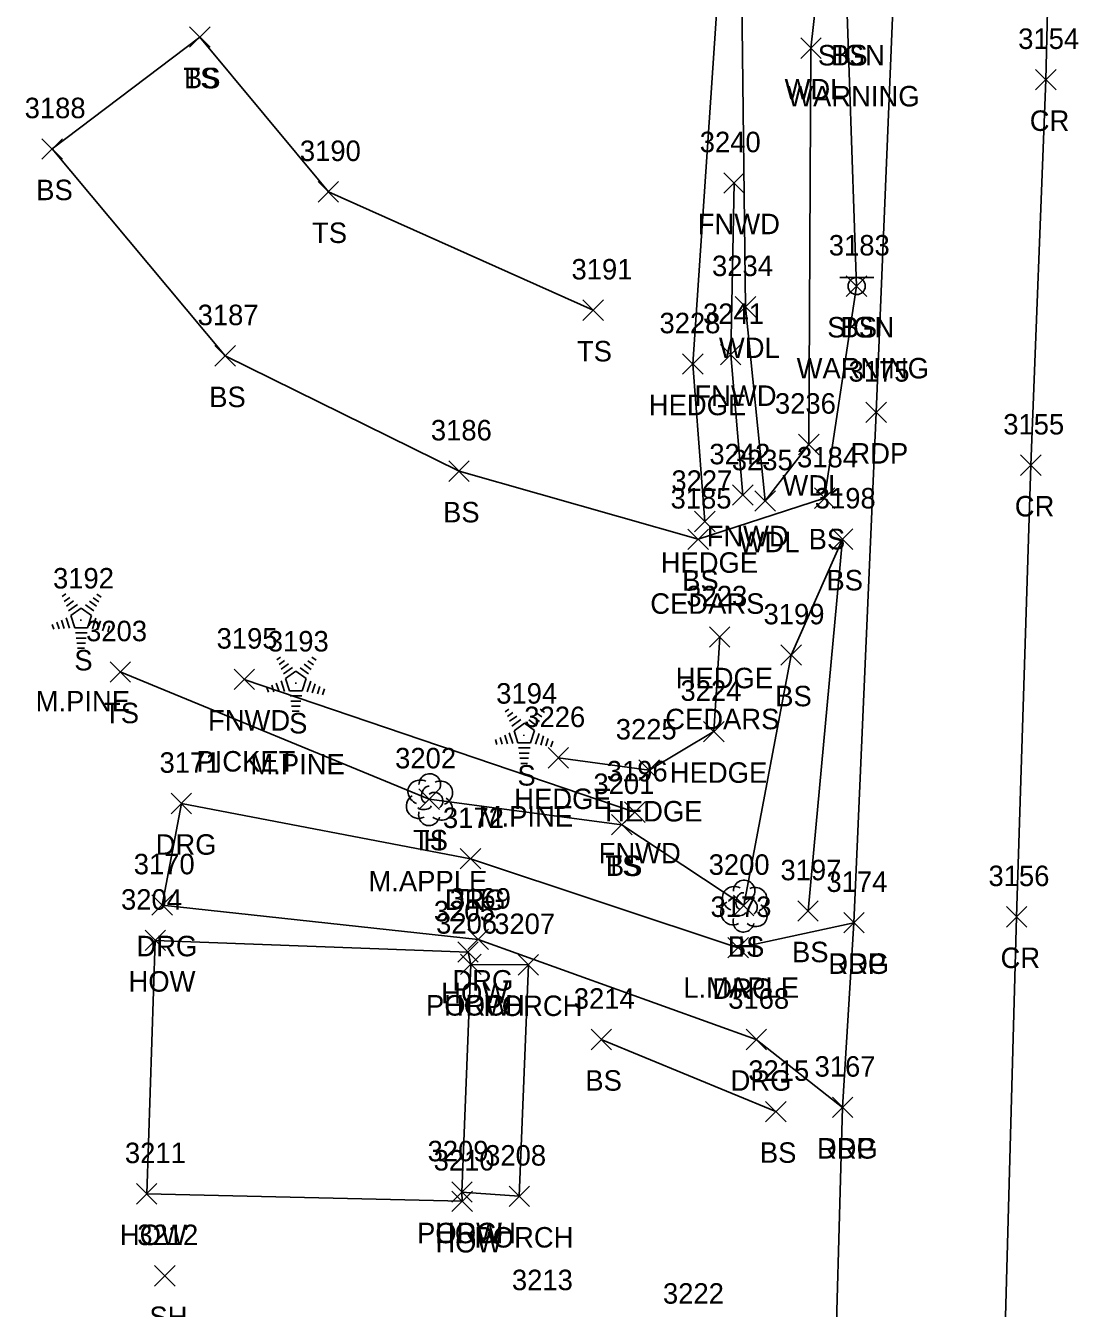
# Model space of a CAD drawing. Extents: x 1609623 to 1616187, y 756677 to 762826.
# Drawn here: x 1610516.2 to 1610618.9, y 762230.4 to 762355.6 of the extents above; entities that cross this region are included whole.
import ezdxf

# ---------------------------------------------------------------- set-up
doc = ezdxf.new("R2010")
doc.units = 0
for name, color, linetype in [('L_A', 7, 'Continuous'), ('L_C', 7, 'Continuous'), ('L_I', 7, 'Continuous'), ('L_TIC', 7, 'Continuous'), ('LAHR', 7, 'Continuous'), ('LAWA', 7, 'Continuous'), ('LBC', 7, 'Continuous'), ('LBF', 7, 'Continuous'), ('LELB', 7, 'Continuous'), ('LFNC', 7, 'Continuous'), ('LTC', 7, 'Continuous'), ('LTD', 7, 'Continuous'), ('P_A', 7, 'Continuous'), ('P_I', 7, 'Continuous'), ('P_TIC', 7, 'Continuous'), ('PET', 7, 'Continuous'), ('PRC', 7, 'Continuous'), ('R_A', 7, 'Continuous'), ('R_I', 7, 'Continuous'), ('R_TIC', 7, 'Continuous'), ('RDG', 7, 'Continuous'), ('S_A', 7, 'Continuous'), ('S_C', 7, 'Continuous'), ('S_I', 7, 'Continuous'), ('SSGN', 7, 'Continuous')]:
    doc.layers.add(name, color=color, linetype=linetype)

msp = doc.modelspace()

# ---------------------------------------------------------------- linework, layer by layer
at = {"layer": 'L_TIC'}
for points in [[(1610532.17, 762353.47), (1610534.17, 762355.47)], [(1610534.17, 762353.47), (1610532.17, 762355.47)], [(1610532.17, 762353.47), (1610534.17, 762355.47)], [(1610534.17, 762353.47), (1610532.17, 762355.47)], [(1610591.83, 762352.39), (1610593.83, 762354.39)], [(1610593.83, 762352.39), (1610591.83, 762354.39)], [(1610517.75, 762342.55), (1610519.75, 762344.55)], [(1610519.75, 762342.55), (1610517.75, 762344.55)], [(1610544.71, 762338.37), (1610546.71, 762340.37)], [(1610546.71, 762338.37), (1610544.71, 762340.37)], [(1610584.32, 762339.23), (1610586.32, 762341.23)], [(1610586.32, 762339.23), (1610584.32, 762341.23)], [(1610596.27, 762329.15), (1610598.27, 762331.15)], [(1610598.27, 762329.15), (1610596.27, 762331.15)], [(1610585.43, 762327.14), (1610587.43, 762329.14)], [(1610587.43, 762327.14), (1610585.43, 762329.14)], [(1610570.57, 762326.81), (1610572.57, 762328.81)], [(1610572.57, 762326.81), (1610570.57, 762328.81)], [(1610534.64, 762322.35), (1610536.64, 762324.35)], [(1610536.64, 762322.35), (1610534.64, 762324.35)], [(1610583.99, 762322.47), (1610585.99, 762324.47)], [(1610585.99, 762322.47), (1610583.99, 762324.47)], [(1610580.3, 762321.56), (1610582.3, 762323.56)], [(1610582.3, 762321.56), (1610580.3, 762323.56)], [(1610591.62, 762313.71), (1610593.62, 762315.71)], [(1610593.62, 762313.71), (1610591.62, 762315.71)], [(1610557.47, 762311.1), (1610559.47, 762313.1)], [(1610559.47, 762311.1), (1610557.47, 762313.1)], [(1610585.17, 762308.77), (1610587.17, 762310.77)], [(1610587.17, 762308.77), (1610585.17, 762310.77)], [(1610587.36, 762308.19), (1610589.36, 762310.19)], [(1610589.36, 762308.19), (1610587.36, 762310.19)], [(1610593.16, 762308.47), (1610595.16, 762310.47)], [(1610595.16, 762308.47), (1610593.16, 762310.47)], [(1610581.46, 762306.18), (1610583.46, 762308.18)], [(1610583.46, 762306.18), (1610581.46, 762308.18)], [(1610580.81, 762304.45), (1610582.81, 762306.45)], [(1610582.81, 762304.45), (1610580.81, 762306.45)], [(1610594.9, 762304.46), (1610596.9, 762306.46)], [(1610596.9, 762304.46), (1610594.9, 762306.46)], [(1610582.92, 762294.91), (1610584.92, 762296.91)], [(1610584.92, 762294.91), (1610582.92, 762296.91)], [(1610589.9, 762293.15), (1610591.9, 762295.15)], [(1610591.9, 762293.15), (1610589.9, 762295.15)], [(1610524.4, 762291.5), (1610526.4, 762293.5)], [(1610526.4, 762291.5), (1610524.4, 762293.5)], [(1610536.5, 762290.78), (1610538.5, 762292.78)], [(1610538.5, 762290.78), (1610536.5, 762292.78)], [(1610582.35, 762285.68), (1610584.35, 762287.68)], [(1610584.35, 762285.68), (1610582.35, 762287.68)], [(1610567.16, 762283.12), (1610569.16, 762285.12)], [(1610569.16, 762283.12), (1610567.16, 762285.12)], [(1610576.03, 762281.91), (1610578.03, 762283.91)], [(1610578.03, 762281.91), (1610576.03, 762283.91)], [(1610554.56, 762279.09), (1610556.56, 762281.09)], [(1610556.56, 762279.09), (1610554.56, 762281.09)], [(1610574.64, 762277.82), (1610576.64, 762279.82)], [(1610576.64, 762277.82), (1610574.64, 762279.82)], [(1610573.36, 762276.59), (1610575.36, 762278.59)], [(1610575.36, 762276.59), (1610573.36, 762278.59)], [(1610573.36, 762276.59), (1610575.36, 762278.59)], [(1610575.36, 762276.59), (1610573.36, 762278.59)], [(1610585.26, 762268.7), (1610587.26, 762270.7)], [(1610587.26, 762268.7), (1610585.26, 762270.7)], [(1610591.54, 762268.17), (1610593.54, 762270.17)], [(1610593.54, 762268.17), (1610591.54, 762270.17)], [(1610527.81, 762265.3), (1610529.81, 762267.3)], [(1610529.81, 762265.3), (1610527.81, 762267.3)], [(1610558.35, 762264.16), (1610560.35, 762266.16)], [(1610560.35, 762264.16), (1610558.35, 762266.16)], [(1610558.62, 762262.96), (1610560.62, 762264.96)], [(1610560.62, 762262.96), (1610558.62, 762264.96)], [(1610558.62, 762262.96), (1610560.62, 762264.96)], [(1610560.62, 762262.96), (1610558.62, 762264.96)], [(1610564.24, 762262.92), (1610566.24, 762264.92)], [(1610566.24, 762262.92), (1610564.24, 762264.92)], [(1610571.36, 762255.63), (1610573.36, 762257.63)], [(1610573.36, 762255.63), (1610571.36, 762257.63)], [(1610588.4, 762248.59), (1610590.4, 762250.59)], [(1610590.4, 762248.59), (1610588.4, 762250.59)], [(1610526.98, 762240.56), (1610528.98, 762242.56)], [(1610528.98, 762240.56), (1610526.98, 762242.56)], [(1610557.75, 762240.74), (1610559.75, 762242.74)], [(1610559.75, 762240.74), (1610557.75, 762242.74)], [(1610557.75, 762240.74), (1610559.75, 762242.74)], [(1610559.75, 762240.74), (1610557.75, 762242.74)], [(1610557.77, 762239.84), (1610559.77, 762241.84)], [(1610559.77, 762239.84), (1610557.77, 762241.84)], [(1610563.35, 762240.32), (1610565.35, 762242.32)], [(1610565.35, 762240.32), (1610563.35, 762242.32)], [(1610528.75, 762232.56), (1610530.75, 762234.56)], [(1610530.75, 762232.56), (1610528.75, 762234.56)]]:
    msp.add_lwpolyline(points, dxfattribs=at)
at = {"layer": 'LAHR'}
for points in [[(1610582.46, 762307.18), (1610581.3, 762322.56), (1610584, 762362.56)], [(1610583.92, 762295.91), (1610583.35, 762286.68), (1610577.03, 762282.91), (1610568.16, 762284.12)]]:
    msp.add_lwpolyline(points, dxfattribs=at)
at = {"layer": 'LAWA'}
msp.add_lwpolyline([(1610586.06, 762360.93), (1610586.43, 762328.14), (1610588.36, 762309.19), (1610592.62, 762314.71), (1610592.83, 762353.39), (1610596.84, 762389.23), (1610588.56, 762386.37)], dxfattribs=at)
at = {"layer": 'LBC'}
for points in [[(1610528.81, 762266.3), (1610559.35, 762265.16), (1610559.62, 762263.96), (1610558.75, 762241.74), (1610558.77, 762240.84), (1610527.98, 762241.56)], [(1610527.98, 762241.56), (1610528.81, 762266.3)]]:
    msp.add_lwpolyline(points, dxfattribs=at)
at = {"layer": 'LBF'}
msp.add_lwpolyline([(1610559.62, 762263.96), (1610565.24, 762263.92), (1610564.35, 762241.32), (1610558.75, 762241.74)], dxfattribs=at)
at = {"layer": 'LELB'}
for points in [[(1610601.24, 762435.51), (1610599.89, 762394.24), (1610598.64, 762372.13), (1610596.35, 762356.7), (1610597.27, 762330.15), (1610594.16, 762309.47), (1610581.81, 762305.45), (1610558.47, 762312.1), (1610535.64, 762323.35), (1610518.75, 762343.55), (1610533.17, 762354.47)], [(1610533.17, 762354.47), (1610545.71, 762339.37), (1610571.57, 762327.81)], [(1610592.54, 762269.17), (1610595.9, 762305.46), (1610590.9, 762294.15), (1610586.26, 762269.7), (1610574.36, 762277.59)], [(1610574.36, 762277.59), (1610555.56, 762280.09), (1610525.4, 762292.5)], [(1610572.36, 762256.63), (1610589.4, 762249.59)]]:
    msp.add_lwpolyline(points, dxfattribs=at)
at = {"layer": 'LFNC'}
for points in [[(1610585.32, 762340.23), (1610584.99, 762323.47), (1610586.17, 762309.77)], [(1610537.5, 762291.78), (1610575.64, 762278.82)]]:
    msp.add_lwpolyline(points, dxfattribs=at)
at = {"layer": 'LTC'}
for p, q in [((1610519.72, 762299.86), (1610520.07, 762300.12)), ((1610519.93, 762299.39), (1610520.46, 762299.78)), ((1610520.14, 762298.93), (1610520.84, 762299.44)), ((1610520.35, 762298.46), (1610521.23, 762299.1)), ((1610522.01, 762299.05), (1610522.81, 762298.46)), ((1610522.38, 762299.4), (1610523.06, 762298.91)), ((1610522.75, 762299.75), (1610523.3, 762299.35)), ((1610523.12, 762300.1), (1610523.54, 762299.79)), ((1610520.12, 762297.79), (1610520.45, 762296.77)), ((1610520.57, 762298.01), (1610521.59, 762298.74)), ((1610520.57, 762298.01), (1610520.96, 762296.81)), ((1610521.59, 762298.74), (1610522.58, 762298.02)), ((1610522.58, 762298.02), (1610522.19, 762296.81)), ((1610523.02, 762297.74), (1610522.68, 762296.7)), ((1610518.75, 762297.14), (1610518.9, 762296.67)), ((1610519.21, 762297.35), (1610519.42, 762296.7)), ((1610519.66, 762297.57), (1610519.93, 762296.73)), ((1610522.19, 762296.81), (1610520.96, 762296.81)), ((1610523.46, 762297.49), (1610523.18, 762296.61)), ((1610523.91, 762297.24), (1610523.67, 762296.51)), ((1610524.35, 762296.99), (1610524.17, 762296.42)), ((1610522.15, 762296.31), (1610521.01, 762296.31)), ((1610522.07, 762295.81), (1610521.08, 762295.81)), ((1610521.99, 762295.31), (1610521.15, 762295.31)), ((1610521.9, 762294.81), (1610521.23, 762294.81)), ((1610540.69, 762293.7), (1610541.04, 762293.96)), ((1610544.09, 762293.94), (1610544.51, 762293.64)), ((1610540.9, 762293.24), (1610541.43, 762293.62)), ((1610541.11, 762292.77), (1610541.81, 762293.28)), ((1610541.32, 762292.31), (1610542.2, 762292.95)), ((1610542.97, 762292.9), (1610543.78, 762292.31)), ((1610543.34, 762293.25), (1610544.02, 762292.75)), ((1610543.72, 762293.6), (1610544.26, 762293.2)), ((1610540.63, 762291.42), (1610540.9, 762290.58)), ((1610541.09, 762291.63), (1610541.42, 762290.61)), ((1610541.54, 762291.85), (1610542.55, 762292.59)), ((1610541.54, 762291.85), (1610541.93, 762290.66)), ((1610542.55, 762292.59), (1610543.55, 762291.86)), ((1610543.55, 762291.86), (1610543.16, 762290.66)), ((1610543.99, 762291.59), (1610543.65, 762290.55)), ((1610539.72, 762290.98), (1610539.87, 762290.52)), ((1610540.18, 762291.2), (1610540.39, 762290.55)), ((1610543.16, 762290.66), (1610541.93, 762290.66)), ((1610543.12, 762290.16), (1610541.98, 762290.16)), ((1610544.43, 762291.34), (1610544.14, 762290.46)), ((1610544.88, 762291.09), (1610544.64, 762290.36)), ((1610545.32, 762290.84), (1610545.13, 762290.27)), ((1610543.04, 762289.66), (1610542.05, 762289.66)), ((1610542.95, 762289.16), (1610542.12, 762289.16)), ((1610562.98, 762288.62), (1610563.34, 762288.88)), ((1610566.38, 762288.86), (1610566.8, 762288.56)), ((1610542.87, 762288.66), (1610542.19, 762288.66)), ((1610563.19, 762288.16), (1610563.72, 762288.54)), ((1610563.4, 762287.69), (1610564.11, 762288.2)), ((1610563.61, 762287.22), (1610564.49, 762287.86)), ((1610565.27, 762287.82), (1610566.08, 762287.23)), ((1610565.64, 762288.17), (1610566.32, 762287.67)), ((1610566.01, 762288.51), (1610566.56, 762288.11)), ((1610563.38, 762286.55), (1610563.71, 762285.53)), ((1610563.84, 762286.77), (1610564.85, 762287.5)), ((1610563.84, 762286.77), (1610564.22, 762285.58)), ((1610564.85, 762287.5), (1610565.85, 762286.78)), ((1610565.85, 762286.78), (1610565.45, 762285.58)), ((1610566.28, 762286.51), (1610565.95, 762285.47)), ((1610562.02, 762285.9), (1610562.17, 762285.43)), ((1610562.47, 762286.12), (1610562.68, 762285.47)), ((1610562.93, 762286.33), (1610563.2, 762285.5)), ((1610565.45, 762285.58), (1610564.22, 762285.58)), ((1610566.73, 762286.26), (1610566.44, 762285.37)), ((1610567.17, 762286.01), (1610566.94, 762285.28)), ((1610567.62, 762285.76), (1610567.43, 762285.18)), ((1610565.42, 762285.08), (1610564.27, 762285.08)), ((1610565.33, 762284.58), (1610564.34, 762284.58)), ((1610565.25, 762284.08), (1610564.42, 762284.08)), ((1610565.16, 762283.58), (1610564.49, 762283.58))]:
    msp.add_line(p, q, dxfattribs=at)
at = {"layer": 'LTD'}
for p, q in [((1610555.56, 762280.09), (1610555.56, 762280.09)), ((1610555.56, 762280.09), (1610555.56, 762280.09)), ((1610586.26, 762269.7), (1610586.26, 762269.7)), ((1610586.26, 762269.7), (1610586.26, 762269.7))]:
    msp.add_line(p, q, dxfattribs=at)
for centre in [(1610555.61, 762281.52), (1610586.31, 762271.13)]:
    msp.add_arc(centre, 1.05, 335.5272, 180.9563, dxfattribs=at)
for centre, major_axis, ratio, start_param, end_param in [((1610554.77, 762280.75), (1.21, -0.51), 0.895232, 1.570796, 4.712389), ((1610555.36, 762280.55), (-0.208, -0.792), 0.645439, 3.141593, 6.283185), ((1610556.61, 762280.67), (-1.14, -0.48), 0.949671, 1.570796, 4.712389), ((1610554.48, 762279.38), (0.58, -1.04), 0.959034, 3.141593, 6.283185), ((1610556.06, 762279.92), (-0.5, 0.667), 0.989748, 3.141593, 6.283185), ((1610556.56, 762279.25), (-1.09, 0.79), 0.841452, 1.570796, 4.712389), ((1610555.56, 762278.59), (0.26, 1.06), 0.942809, 1.570796, 4.712389), ((1610555.11, 762279.34), (-0.625, -0.083), 0.423636, 0, 3.141593), ((1610585.47, 762270.36), (1.21, -0.51), 0.895232, 1.570796, 4.712389), ((1610587.31, 762270.28), (-1.14, -0.48), 0.949671, 1.570796, 4.712389), ((1610586.06, 762270.15), (-0.208, -0.792), 0.645439, 3.141593, 6.283185), ((1610586.76, 762269.53), (-0.5, 0.667), 0.989748, 3.141593, 6.283185), ((1610585.18, 762268.99), (0.58, -1.04), 0.959034, 3.141593, 6.283185), ((1610585.81, 762268.95), (-0.625, -0.083), 0.423636, 0, 3.141593), ((1610587.26, 762268.86), (-1.09, 0.79), 0.841452, 1.570796, 4.712389), ((1610586.26, 762268.2), (0.26, 1.06), 0.942809, 1.570796, 4.712389)]:
    msp.add_ellipse(centre, major_axis=major_axis, ratio=ratio, start_param=start_param, end_param=end_param, dxfattribs=at)
at = {"layer": 'P_TIC'}
for points in [[(1610614.76, 762349.31), (1610616.76, 762351.31)], [(1610616.76, 762349.31), (1610614.76, 762351.31)], [(1610598.19, 762316.84), (1610600.19, 762318.84)], [(1610600.19, 762316.84), (1610598.19, 762318.84)], [(1610613.29, 762311.68), (1610615.29, 762313.68)], [(1610615.29, 762311.68), (1610613.29, 762313.68)], [(1610596.03, 762267.03), (1610598.03, 762269.03)], [(1610598.03, 762267.03), (1610596.03, 762269.03)], [(1610611.91, 762267.6), (1610613.91, 762269.6)], [(1610613.91, 762267.6), (1610611.91, 762269.6)], [(1610594.92, 762249), (1610596.92, 762251)], [(1610596.92, 762249), (1610594.92, 762251)]]:
    msp.add_lwpolyline(points, dxfattribs=at)
at = {"layer": 'PET'}
msp.add_lwpolyline([(1610595.04, 762218.43), (1610595.92, 762250), (1610597.03, 762268.03), (1610599.19, 762317.84), (1610601.02, 762361.92), (1610601.97, 762392.04), (1610603.58, 762435.72)], dxfattribs=at)
at = {"layer": 'PRC'}
msp.add_lwpolyline([(1610616.88, 762447.82), (1610616.9, 762397.77), (1610615.76, 762350.31), (1610614.29, 762312.68), (1610612.91, 762268.6), (1610611.57, 762220.08)], dxfattribs=at)
at = {"layer": 'R_TIC'}
for points in [[(1610530.36, 762278.66), (1610532.36, 762280.66)], [(1610532.36, 762278.66), (1610530.36, 762280.66)], [(1610558.59, 762273.27), (1610560.59, 762275.27)], [(1610560.59, 762273.27), (1610558.59, 762275.27)], [(1610528.49, 762268.75), (1610530.49, 762270.75)], [(1610530.49, 762268.75), (1610528.49, 762270.75)], [(1610596.03, 762267.03), (1610598.03, 762269.03)], [(1610598.03, 762267.03), (1610596.03, 762269.03)], [(1610559.33, 762265.4), (1610561.33, 762267.4)], [(1610561.33, 762265.4), (1610559.33, 762267.4)], [(1610584.72, 762264.59), (1610586.72, 762266.59)], [(1610586.72, 762264.59), (1610584.72, 762266.59)], [(1610586.49, 762255.63), (1610588.49, 762257.63)], [(1610588.49, 762255.63), (1610586.49, 762257.63)], [(1610594.92, 762249), (1610596.92, 762251)], [(1610596.92, 762249), (1610594.92, 762251)]]:
    msp.add_lwpolyline(points, dxfattribs=at)
at = {"layer": 'RDG'}
msp.add_lwpolyline([(1610595.92, 762250), (1610587.49, 762256.63), (1610560.33, 762266.4), (1610529.49, 762269.75), (1610531.36, 762279.66), (1610559.59, 762274.27), (1610585.72, 762265.59), (1610597.03, 762268.03)], dxfattribs=at)
at = {"layer": 'SSGN'}
for p, q in [((1610595.64, 762331), (1610598.97, 762331)), ((1610597.29, 762330.17), (1610597.29, 762330.17))]:
    msp.add_line(p, q, dxfattribs=at)
msp.add_circle((1610597.29, 762330.17), 0.833, dxfattribs=at)

# ---------------------------------------------------------------- texts
at = {"layer": 'L_A'}
for s, p in [('BS', (1610594.79, 762351.7)), ('TS', (1610531.57, 762349.47)), ('BS', (1610531.61, 762349.47)), ('WDL', (1610590.25, 762348.39)), ('BS', (1610517.19, 762338.55)), ('FNWD', (1610581.78, 762335.23)), ('TS', (1610544.12, 762334.37)), ('BS', (1610595.71, 762325.15)), ('TS', (1610569.98, 762322.81)), ('WDL', (1610583.84, 762323.14)), ('BS', (1610534.08, 762318.35)), ('FNWD', (1610581.45, 762318.47)), ('HEDGE', (1610577, 762317.56)), ('WDL', (1610590.04, 762309.71)), ('BS', (1610556.91, 762307.1)), ('FNWD', (1610582.64, 762304.77)), ('BS', (1610592.6, 762304.47)), ('WDL', (1610585.77, 762304.19)), ('HEDGE', (1610578.16, 762302.18)), ('BS', (1610580.25, 762300.45)), ('BS', (1610594.34, 762300.46)), ('S', (1610520.91, 762292.65)), ('HEDGE', (1610579.62, 762290.91)), ('BS', (1610589.34, 762289.15)), ('TS', (1610523.81, 762287.5)), ('FNWD', (1610533.96, 762286.78)), ('S', (1610541.88, 762286.5)), ('S', (1610564.17, 762281.41)), ('HEDGE', (1610579.05, 762281.68)), ('HEDGE', (1610563.86, 762279.12)), ('HEDGE', (1610572.73, 762277.91)), ('TS', (1610553.97, 762275.09)), ('H', (1610555, 762275.09)), ('FNWD', (1610572.1, 762273.82)), ('TS', (1610572.77, 762272.59)), ('BS', (1610572.8, 762272.59)), ('BS', (1610584.71, 762264.7)), ('H', (1610585.7, 762264.7)), ('BS', (1610590.98, 762264.17)), ('HOW', (1610526.2, 762261.3)), ('HOW', (1610556.73, 762260.16)), ('PORCH', (1610555.24, 762258.96)), ('HOW', (1610557, 762258.96)), ('PORCH', (1610560.86, 762258.92)), ('BS', (1610570.8, 762251.63)), ('BS', (1610587.84, 762244.59)), ('PORCH', (1610554.37, 762236.74)), ('HOW', (1610556.13, 762236.74)), ('HOW', (1610525.36, 762236.56)), ('HOW', (1610556.16, 762235.84)), ('PORCH', (1610559.98, 762236.32)), ('SH', (1610528.24, 762228.56))]:
    msp.add_text(s, height=2, dxfattribs=at).set_placement(p)
at = {"layer": 'L_C'}
for s, p in [('CEDARS', (1610577.14, 762298.18)), ('M.PINE', (1610517.13, 762288.65)), ('CEDARS', (1610578.6, 762286.91)), ('PICKET', (1610532.83, 762282.78)), ('M.PINE', (1610538.1, 762282.5)), ('M.PINE', (1610560.39, 762277.41)), ('M.APPLE', (1610549.63, 762271.09)), ('L.MAPLE', (1610580.37, 762260.7))]:
    msp.add_text(s, height=2, dxfattribs=at).set_placement(p)
at = {"layer": 'L_I'}
for s, p in [('3188', (1610516.06, 762346.55)), ('3240', (1610581.97, 762343.23)), ('3190', (1610542.93, 762342.37)), ('3183', (1610594.57, 762333.15)), ('3191', (1610569.45, 762330.81)), ('3234', (1610583.17, 762331.14)), ('3187', (1610532.95, 762326.35)), ('3241', (1610582.29, 762326.47)), ('3228', (1610578.04, 762325.56)), ('3236', (1610589.31, 762317.71)), ('3186', (1610555.72, 762315.1)), ('3242', (1610582.91, 762312.77)), ('3235', (1610585.1, 762312.19)), ('3184', (1610591.47, 762312.47)), ('3227', (1610579.2, 762310.18)), ('3185', (1610579.12, 762308.45)), ('3198', (1610593.2, 762308.46)), ('3192', (1610518.83, 762300.65)), ('3223', (1610580.66, 762298.91)), ('3199', (1610588.2, 762297.15)), ('3203', (1610522.06, 762295.5)), ('3195', (1610534.8, 762294.78)), ('3193', (1610539.8, 762294.5)), ('3194', (1610562.1, 762289.41)), ('3224', (1610580.09, 762289.68)), ('3226', (1610564.84, 762287.12)), ('3225', (1610573.77, 762285.91)), ('3202', (1610552.23, 762283.09)), ('3202', (1610552.23, 762283.09)), ('3196', (1610572.89, 762281.82)), ('3201', (1610571.59, 762280.59)), ('3201', (1610571.59, 762280.59)), ('3200', (1610582.84, 762272.7)), ('3200', (1610582.84, 762272.7)), ('3197', (1610589.85, 762272.17)), ('3204', (1610525.47, 762269.3)), ('3205', (1610556.01, 762268.16)), ('3206', (1610556.23, 762266.96)), ('3206', (1610556.23, 762266.96)), ('3207', (1610561.9, 762266.92)), ('3214', (1610569.67, 762259.63)), ('3215', (1610586.71, 762252.59)), ('3211', (1610525.85, 762244.56)), ('3209', (1610555.4, 762244.74)), ('3209', (1610555.4, 762244.74)), ('3208', (1610561.02, 762244.32)), ('3210', (1610555.99, 762243.84)), ('3212', (1610527.06, 762236.56)), ('3213', (1610563.63, 762232.16)), ('3222', (1610578.38, 762230.84))]:
    msp.add_text(s, height=2, dxfattribs=at).set_placement(p)
at = {"layer": 'LTC'}
for p in [(1610521.47, 762297.75), (1610542.44, 762291.6), (1610564.73, 762286.52)]:
    msp.add_text('.', height=1.04, rotation=270, dxfattribs=at).set_placement(p)
at = {"layer": 'P_A'}
for s, p in [('CR', (1610614.19, 762345.31)), ('RDP', (1610596.68, 762312.84)), ('CR', (1610612.73, 762307.68)), ('CR', (1610611.34, 762263.6)), ('RDP', (1610594.52, 762263.03)), ('RDP', (1610593.41, 762245))]:
    msp.add_text(s, height=2, dxfattribs=at).set_placement(p)
at = {"layer": 'P_I'}
for s, p in [('3154', (1610613.06, 762353.31)), ('3175', (1610596.5, 762320.84)), ('3155', (1610611.6, 762315.68)), ('3174', (1610594.34, 762271.03)), ('3156', (1610610.16, 762271.6)), ('3167', (1610593.18, 762253))]:
    msp.add_text(s, height=2, dxfattribs=at).set_placement(p)
at = {"layer": 'R_A'}
for p in [(1610528.85, 762274.66), (1610557.08, 762269.27), (1610526.97, 762264.75), (1610594.52, 762263.03), (1610557.82, 762261.4), (1610583.2, 762260.59), (1610584.98, 762251.63), (1610593.41, 762245)]:
    msp.add_text('DRG', height=2, dxfattribs=at).set_placement(p)
at = {"layer": 'R_I'}
for s, p in [('3171', (1610529.23, 762282.66)), ('3172', (1610556.9, 762277.27)), ('3170', (1610526.71, 762272.75)), ('3174', (1610594.34, 762271.03)), ('3169', (1610557.58, 762269.4)), ('3173', (1610583.02, 762268.59)), ('3168', (1610584.75, 762259.63)), ('3167', (1610593.18, 762253))]:
    msp.add_text(s, height=2, dxfattribs=at).set_placement(p)
at = {"layer": 'S_A'}
for p in [(1610593.5, 762351.7), (1610594.42, 762325.15)]:
    msp.add_text('SIGN', height=2, dxfattribs=at).set_placement(p)
at = {"layer": 'S_C'}
for p in [(1610590.51, 762347.7), (1610591.43, 762321.15)]:
    msp.add_text('WARNING', height=2, dxfattribs=at).set_placement(p)
at = {"layer": 'S_I'}
msp.add_text('3183', height=2, dxfattribs=at).set_placement((1610594.57, 762333.15))

doc.saveas('drawing.dxf')
